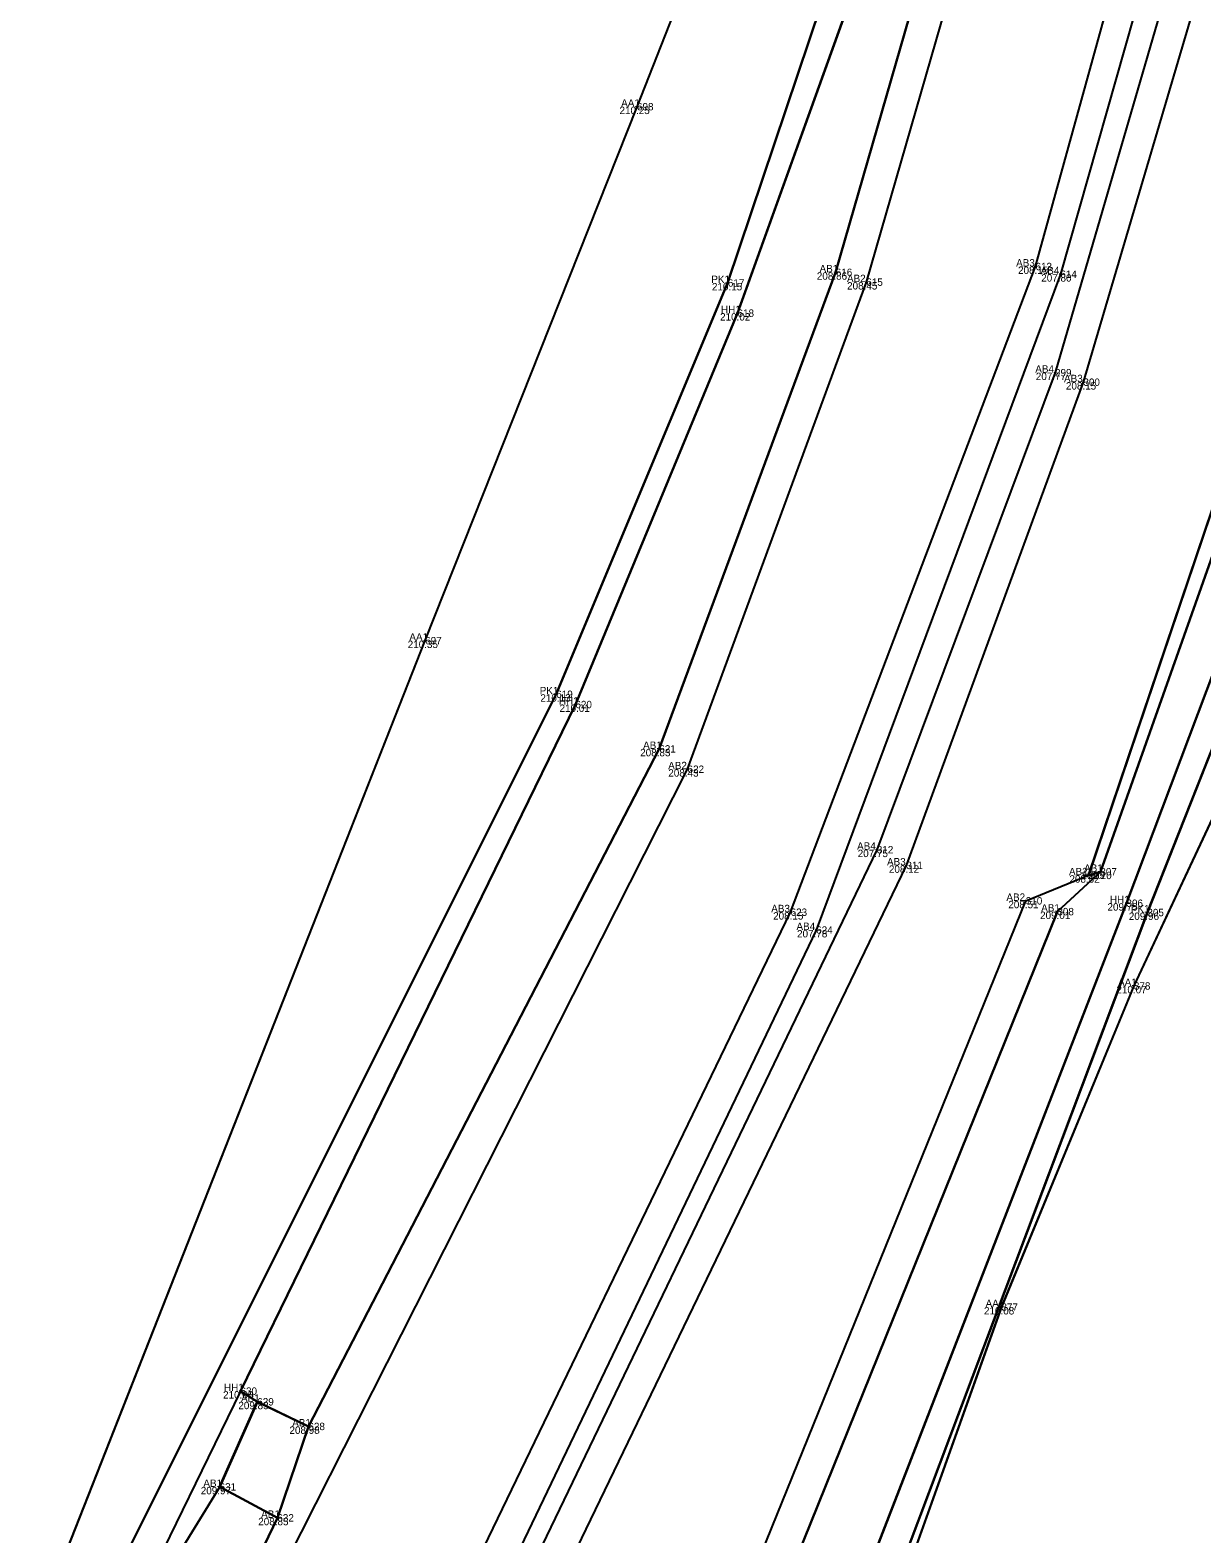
# Model space of a CAD drawing. Extents: x -263091 to -262565, y -1238731 to -1237092.
# Drawn here: x -262869.55 to -262837.85, y -1238112.64 to -1238071.97 of the extents above; entities that cross this region are included whole.
import ezdxf

# ---------------------------------------------------------------- set-up
doc = ezdxf.new("R2010")
doc.units = 0
for name, color, linetype in [('01_Hrana_betónu', 7, 'Continuous'), ('02_Oplotenie', 7, 'Continuous'), ('03_Asfalt', 7, 'Continuous'), ('05_Hrana_terénu', 7, 'Continuous'), ('07_Iné', 7, 'Continuous'), ('09_Múrik', 7, 'Continuous'), ('Groma (21)', 7, 'Continuous'), ('Groma (22)', 7, 'Continuous'), ('Groma (23)', 7, 'Continuous'), ('Groma (24)', 7, 'Continuous'), ('U003_Betónové_múriky', 7, 'Continuous'), ('U003_Betónové_panely', 7, 'Continuous'), ('U003_Betóny_prídavné', 7, 'Continuous'), ('U003_Zeleň_mimo', 7, 'Continuous'), ('U003_Zeleň_vnútro', 7, 'Continuous'), ('U003_Zeleň_zatrávňovač', 7, 'Continuous'), ('U005_Betóny_prídavné', 7, 'Continuous')]:
    doc.layers.add(name, color=color, linetype=linetype)

msp = doc.modelspace()

# ---------------------------------------------------------------- linework, layer by layer
at = {"layer": '01_Hrana_betónu'}
for points in [[(-262903.088, -1238238.797), (-262890.817, -1238204.479), (-262885.468, -1238189.492), (-262878.003, -1238168.56), (-262870.455, -1238147.513), (-262864.947, -1238132.168), (-262859.037, -1238116.651), (-262848.977, -1238095.826), (-262842.353, -1238078.361), (-262839.446, -1238067.823), (-262836.783, -1238055.069), (-262834.905, -1238040.999), (-262833.763, -1238025.462), (-262832.297, -1238000.555), (-262831.13, -1237981.111), (-262829.791, -1237958.391), (-262828.651, -1237937.03), (-262828.571, -1237935.876)], [(-262827.762, -1237935.927), (-262827.853, -1237937.062), (-262829.049, -1237958.415), (-262830.305, -1237981.211), (-262831.433, -1238000.629), (-262832.987, -1238025.43), (-262834.086, -1238041.027), (-262836.169, -1238055.023), (-262838.684, -1238068.024), (-262841.681, -1238078.569), (-262848.285, -1238096.308), (-262858.162, -1238116.913), (-262863.876, -1238132.122), (-262869.919, -1238147.692), (-262877.244, -1238168.638), (-262884.69, -1238189.67), (-262901.991, -1238238.762)], [(-262827.034, -1237935.973), (-262827.072, -1237937.036), (-262828.491, -1237960.168), (-262829.643, -1237980.454), (-262830.754, -1238002.123), (-262832.4, -1238026.024), (-262833.369, -1238041.644), (-262835.263, -1238055.011), (-262838.048, -1238068.261), (-262841.826, -1238081.232), (-262846.645, -1238094.136), (-262857.777, -1238117.273), (-262863.292, -1238131.948), (-262884.082, -1238190.299), (-262901.352, -1238238.742)], [(-262900.376, -1238238.711), (-262890.192, -1238209.46), (-262883.463, -1238190.564), (-262868.512, -1238148.877), (-262862.514, -1238132.276), (-262857.014, -1238117.706), (-262845.846, -1238094.561), (-262841.058, -1238081.49), (-262837.218, -1238068.474), (-262834.492, -1238055.416), (-262832.606, -1238041.772), (-262831.509, -1238026.143), (-262830.024, -1238002.24), (-262828.826, -1237980.518), (-262827.576, -1237960.277), (-262826.117, -1237937.218), (-262826.079, -1237936.033)], [(-262908.762, -1238238.978), (-262904.818, -1238227.708), (-262897.756, -1238208.088), (-262895.676, -1238202.213), (-262890.59, -1238187.74), (-262883.178, -1238166.691), (-262875.605, -1238145.524), (-262870.177, -1238130.111), (-262864.546, -1238115.411), (-262863.698, -1238113.971), (-262862.86, -1238112.208), (-262862.02, -1238109.736), (-262852.529, -1238091.409), (-262847.756, -1238078.518), (-262845.507, -1238070.714), (-262845.277, -1238070.627)], [(-262907.715, -1238238.945), (-262903.959, -1238228.072), (-262896.871, -1238208.378), (-262894.873, -1238202.609), (-262889.743, -1238188.028), (-262882.328, -1238167.085), (-262874.744, -1238145.867), (-262869.274, -1238130.427), (-262863.367, -1238114.899), (-262851.765, -1238091.959), (-262846.929, -1238078.783), (-262844.647, -1238070.871), (-262844.833, -1238070.767)], [(-262896.34, -1238238.582), (-262893.58, -1238232.03), (-262890.694, -1238224.883), (-262885.46, -1238210.629), (-262879.076, -1238191.844), (-262872.3, -1238172.74), (-262864.174, -1238150.334), (-262858.102, -1238133.93), (-262852.288, -1238119.39), (-262842.616, -1238095.519), (-262840.924, -1238094.827)], [(-262895.195, -1238238.545), (-262892.745, -1238232.498), (-262889.857, -1238225.243), (-262884.61, -1238210.939), (-262878.158, -1238192.142), (-262871.406, -1238173.111), (-262863.323, -1238150.734), (-262857.2, -1238134.123), (-262851.463, -1238119.84), (-262841.762, -1238095.81), (-262840.6, -1238094.732)]]:
    msp.add_lwpolyline(points, dxfattribs=at)
at = {"layer": '02_Oplotenie'}
for points in [[(-262912.451, -1238238.295), (-262908.254, -1238226.663), (-262901.526, -1238207.942), (-262898.552, -1238199.602), (-262894.22, -1238186.327), (-262886.794, -1238165.648), (-262879.297, -1238144.201), (-262873.976, -1238128.814), (-262867.141, -1238113.572), (-262855.316, -1238089.931), (-262850.675, -1238078.807), (-262846.261, -1238065.654), (-262843.56, -1238054.226), (-262842.344, -1238048.099), (-262841.445, -1238040.349), (-262840.733, -1238030.077), (-262839.013, -1238000.384), (-262838.353, -1237989.712), (-262835.178, -1237935.879)], [(-262819.762, -1237938.034), (-262820.788, -1237960.675), (-262821.837, -1237980.919), (-262823.308, -1238002.106), (-262824.582, -1238026.068), (-262825.82, -1238041.973), (-262827.772, -1238056.552), (-262830.57, -1238069.546), (-262834.589, -1238083.855), (-262839.328, -1238095.835), (-262848.782, -1238120.942), (-262853.684, -1238135.175), (-262859.896, -1238152.781), (-262867.698, -1238174.329), (-262874.833, -1238193.487), (-262881.88, -1238212.036), (-262887.174, -1238225.693), (-262888.829, -1238230.138)]]:
    msp.add_lwpolyline(points, dxfattribs=at)
at = {"layer": '03_Asfalt'}
for points in [[(-262912.678, -1238239.103), (-262913.356, -1238239.285), (-262915.717, -1238239.279), (-262916.328, -1238238.784), (-262916.575, -1238236.319), (-262915.768, -1238233.661), (-262912.404, -1238225.097), (-262904.805, -1238205.606), (-262896.687, -1238184.948), (-262888.478, -1238163.929), (-262880.124, -1238142.63), (-262874.65, -1238128.675), (-262868.549, -1238113.075), (-262858.861, -1238088.481), (-262853.132, -1238074.038), (-262850.084, -1238066.288), (-262845.869, -1238049.471), (-262845.094, -1238038.662), (-262844.346, -1238028.542), (-262842.599, -1238000.955), (-262841.603, -1237985.168), (-262838.824, -1237943.888), (-262838.24, -1237934.633), (-262838.283, -1237933.488)], [(-262836.859, -1238089.782), (-262836.111, -1238090.171), (-262839.692, -1238097.821), (-262843.275, -1238106.507), (-262847.806, -1238119.202), (-262853.613, -1238135.97), (-262859.461, -1238152.467), (-262860.389, -1238156.54), (-262862.798, -1238164.04), (-262866.716, -1238174.359), (-262874.069, -1238193.289), (-262881.205, -1238211.833), (-262885.932, -1238224.211), (-262887.38, -1238228.337), (-262891.202, -1238238.204), (-262891.593, -1238238.614)]]:
    msp.add_lwpolyline(points, dxfattribs=at)
at = {"layer": '05_Hrana_terénu'}
for points in [[(-262835.062, -1237935.275), (-262834.86, -1237936.333), (-262838.087, -1237989.633), (-262838.484, -1238000.332), (-262840.387, -1238030.181), (-262840.991, -1238040.253), (-262843.126, -1238054.282), (-262845.675, -1238066.436), (-262850.413, -1238079.623), (-262854.798, -1238090.209), (-262863.856, -1238108.78), (-262866.643, -1238114.502), (-262872.333, -1238129.41), (-262877.981, -1238144.625), (-262885.616, -1238166.033), (-262893.121, -1238186.676), (-262898.244, -1238201.149), (-262900.554, -1238208.001), (-262907.375, -1238226.781), (-262911.85, -1238238.364), (-262912.678, -1238239.103)], [(-262849.564, -1238120.544), (-262839.894, -1238095.583), (-262835.301, -1238083.403), (-262831.402, -1238069.334), (-262828.632, -1238056.516), (-262826.436, -1238041.83), (-262825.08, -1238026.06), (-262823.863, -1238001.967), (-262822.633, -1237980.847), (-262821.298, -1237960.54), (-262820.334, -1237939.047), (-262819.871, -1237937.657)]]:
    msp.add_lwpolyline(points, dxfattribs=at)
at = {"layer": '07_Iné'}
msp.add_lwpolyline([(-262862.86, -1238112.208), (-262864.423, -1238111.371), (-262863.403, -1238109.069), (-262862.02, -1238109.736)], dxfattribs=at)
at = {"layer": '09_Múrik'}
for points in [[(-262840.924, -1238094.827), (-262836.941, -1238083.068), (-262832.969, -1238069.042), (-262830.214, -1238056.416), (-262828.063, -1238041.942), (-262826.83, -1238026.465), (-262825.494, -1238001.855), (-262824.316, -1237980.84), (-262823.031, -1237960.337), (-262821.719, -1237936.336)], [(-262840.6, -1238094.732), (-262836.43, -1238082.967), (-262832.633, -1238069.1), (-262829.86, -1238056.421), (-262827.688, -1238042.018), (-262826.338, -1238026.448), (-262825.108, -1238001.872), (-262823.89, -1237980.741), (-262822.602, -1237960.47), (-262821.253, -1237936.39)]]:
    msp.add_lwpolyline(points, dxfattribs=at)
at = {"layer": 'Groma (21)'}
for centre in [(-262853.132, -1238074.038), (-262847.756, -1238078.518), (-262842.353, -1238078.361), (-262841.681, -1238078.569), (-262850.675, -1238078.807), (-262846.929, -1238078.783), (-262850.413, -1238079.623), (-262841.826, -1238081.232), (-262841.058, -1238081.49), (-262858.861, -1238088.481), (-262855.316, -1238089.931), (-262854.798, -1238090.209), (-262852.529, -1238091.409), (-262851.765, -1238091.959), (-262846.645, -1238094.136), (-262845.846, -1238094.561), (-262840.924, -1238094.827), (-262840.6, -1238094.732), (-262842.616, -1238095.519), (-262839.894, -1238095.583), (-262848.977, -1238095.826), (-262841.762, -1238095.81), (-262839.328, -1238095.835), (-262848.285, -1238096.308), (-262839.692, -1238097.821), (-262843.275, -1238106.507), (-262863.856, -1238108.78), (-262863.403, -1238109.069), (-262862.02, -1238109.736), (-262864.423, -1238111.371), (-262862.86, -1238112.208)]:
    msp.add_circle(centre, 0.01, dxfattribs=at)
at = {"layer": 'U003_Betónové_múriky'}
msp.add_lwpolyline([(-262821.25, -1237936.39), (-262822.6, -1237960.47), (-262823.89, -1237980.74), (-262825.11, -1238001.87), (-262826.34, -1238026.45), (-262827.69, -1238042.02), (-262829.86, -1238056.42), (-262832.63, -1238069.1), (-262836.43, -1238082.97), (-262840.6, -1238094.73), (-262840.92, -1238094.83), (-262836.94, -1238083.07), (-262832.97, -1238069.04), (-262830.21, -1238056.42), (-262828.06, -1238041.94), (-262826.83, -1238026.47), (-262825.49, -1238001.86), (-262824.32, -1237980.84), (-262823.03, -1237960.34), (-262821.72, -1237936.34)], close=True, dxfattribs=at)
msp.add_lwpolyline([(-262821.72, -1237936.34), (-262821.25, -1237936.39), (-262822.6, -1237960.47), (-262823.89, -1237980.74), (-262825.11, -1238001.87), (-262826.34, -1238026.45), (-262827.69, -1238042.02), (-262829.86, -1238056.42), (-262832.63, -1238069.1), (-262836.43, -1238082.97), (-262840.6, -1238094.73), (-262840.92, -1238094.83), (-262836.94, -1238083.07), (-262832.97, -1238069.04), (-262830.21, -1238056.42), (-262828.06, -1238041.94), (-262826.83, -1238026.47), (-262825.49, -1238001.86), (-262824.32, -1237980.84), (-262823.03, -1237960.34), (-262821.72, -1237936.34)], dxfattribs=at)
at = {"layer": 'U003_Betónové_panely'}
for points in [[(-262863.7, -1238113.97), (-262862.86, -1238112.21), (-262862.02, -1238109.74), (-262852.53, -1238091.41), (-262847.76, -1238078.52), (-262845.51, -1238070.71), (-262845.28, -1238070.63), (-262844.83, -1238070.77), (-262843.91, -1238066.81), (-262841.25, -1238054.25), (-262839.31, -1238040.16), (-262838.49, -1238030.43), (-262836.61, -1238000.28), (-262836.05, -1237989.86), (-262834, -1237956.68), (-262832.67, -1237935.62), (-262832.64, -1237935.62), (-262832.51, -1237933.84)], [(-262863.7, -1238113.97), (-262862.86, -1238112.21), (-262862.02, -1238109.74), (-262852.53, -1238091.41), (-262847.76, -1238078.52), (-262845.51, -1238070.71), (-262845.28, -1238070.63), (-262844.83, -1238070.77), (-262843.91, -1238066.81), (-262841.25, -1238054.25), (-262839.31, -1238040.16), (-262838.49, -1238030.43), (-262836.61, -1238000.28), (-262836.05, -1237989.86), (-262834, -1237956.68), (-262832.67, -1237935.62), (-262832.64, -1237935.62), (-262832.51, -1237933.84)], [(-262822, -1237934.47), (-262822.23, -1237936.28), (-262821.72, -1237936.34), (-262823.03, -1237960.34), (-262824.32, -1237980.84), (-262825.49, -1238001.86), (-262826.83, -1238026.47), (-262828.06, -1238041.94), (-262830.21, -1238056.42), (-262832.97, -1238069.04), (-262836.94, -1238083.07), (-262840.92, -1238094.83), (-262840.6, -1238094.73), (-262841.76, -1238095.81), (-262851.46, -1238119.84), (-262857.2, -1238134.12), (-262863.32, -1238150.73), (-262871.41, -1238173.11), (-262878.16, -1238192.14), (-262884.61, -1238210.94), (-262889.86, -1238225.24), (-262892.75, -1238232.5), (-262895.19, -1238238.55), (-262900.83, -1238252.4)], [(-262822, -1237934.47), (-262822.23, -1237936.28), (-262821.72, -1237936.34), (-262823.03, -1237960.34), (-262824.32, -1237980.84), (-262825.49, -1238001.86), (-262826.83, -1238026.47), (-262828.06, -1238041.94), (-262830.21, -1238056.42), (-262832.97, -1238069.04), (-262836.94, -1238083.07), (-262840.92, -1238094.83), (-262840.6, -1238094.73), (-262841.76, -1238095.81), (-262851.46, -1238119.84), (-262857.2, -1238134.12), (-262863.32, -1238150.73), (-262871.41, -1238173.11), (-262878.16, -1238192.14), (-262884.61, -1238210.94), (-262889.86, -1238225.24), (-262892.75, -1238232.5), (-262895.19, -1238238.55), (-262900.83, -1238252.4)]]:
    msp.add_lwpolyline(points, dxfattribs=at)
at = {"layer": 'U003_Betóny_prídavné'}
msp.add_lwpolyline([(-262864.42, -1238111.37), (-262863.4, -1238109.07), (-262862.02, -1238109.74), (-262862.86, -1238112.21)], close=True, dxfattribs=at)
at = {"layer": 'U003_Zeleň_mimo'}
for points in [[(-262868.55, -1238113.08), (-262858.86, -1238088.48), (-262853.13, -1238074.04), (-262850.08, -1238066.29), (-262845.87, -1238049.47), (-262845.09, -1238038.66), (-262844.35, -1238028.54), (-262842.6, -1238000.96), (-262841.6, -1237985.17), (-262838.82, -1237943.89), (-262838.24, -1237934.63)], [(-262836.32, -1237934.59), (-262836.29, -1237935.17), (-262835.06, -1237935.28), (-262835.18, -1237935.88), (-262838.35, -1237989.71), (-262839.01, -1238000.38), (-262840.73, -1238030.08), (-262841.45, -1238040.35), (-262842.34, -1238048.1), (-262843.56, -1238054.23), (-262846.26, -1238065.65), (-262850.68, -1238078.81), (-262855.32, -1238089.93), (-262867.14, -1238113.57)], [(-262848.78, -1238120.94), (-262839.33, -1238095.84), (-262834.59, -1238083.86), (-262836.86, -1238089.78), (-262836.11, -1238090.17), (-262839.69, -1238097.82), (-262843.28, -1238106.51), (-262847.81, -1238119.2)]]:
    msp.add_lwpolyline(points, dxfattribs=at)
at = {"layer": 'U003_Zeleň_vnútro'}
for points in [[(-262849.56, -1238120.54), (-262839.89, -1238095.58), (-262835.3, -1238083.4), (-262831.4, -1238069.33), (-262828.63, -1238056.52), (-262826.44, -1238041.83), (-262825.08, -1238026.06), (-262823.86, -1238001.97), (-262822.63, -1237980.85), (-262821.3, -1237960.54), (-262820.33, -1237939.05), (-262819.87, -1237937.66), (-262819.76, -1237938.03), (-262820.79, -1237960.68), (-262821.84, -1237980.92), (-262823.31, -1238002.11), (-262824.58, -1238026.07), (-262825.82, -1238041.97), (-262827.77, -1238056.55), (-262830.57, -1238069.55), (-262834.59, -1238083.86), (-262839.33, -1238095.84), (-262848.78, -1238120.94)], [(-262849.56, -1238120.54), (-262839.89, -1238095.58), (-262835.3, -1238083.4), (-262831.4, -1238069.33), (-262828.63, -1238056.52), (-262826.44, -1238041.83), (-262825.08, -1238026.06), (-262823.86, -1238001.97), (-262822.63, -1237980.85), (-262821.3, -1237960.54), (-262820.33, -1237939.05), (-262819.87, -1237937.66), (-262819.76, -1237938.03), (-262820.79, -1237960.68), (-262821.84, -1237980.92), (-262823.31, -1238002.11), (-262824.58, -1238026.07), (-262825.82, -1238041.97), (-262827.77, -1238056.55), (-262830.57, -1238069.55), (-262834.59, -1238083.86), (-262839.33, -1238095.84), (-262848.78, -1238120.94)], [(-262867.14, -1238113.57), (-262855.32, -1238089.93), (-262850.68, -1238078.81), (-262846.26, -1238065.65), (-262843.56, -1238054.23), (-262842.34, -1238048.1), (-262841.45, -1238040.35), (-262840.73, -1238030.08), (-262839.01, -1238000.38)], [(-262867.14, -1238113.57), (-262855.32, -1238089.93), (-262850.68, -1238078.81), (-262846.26, -1238065.65), (-262843.56, -1238054.23), (-262842.34, -1238048.1), (-262841.45, -1238040.35), (-262840.73, -1238030.08), (-262839.01, -1238000.38)], [(-262838.48, -1238000.33), (-262840.39, -1238030.18), (-262840.99, -1238040.25), (-262843.13, -1238054.28), (-262845.68, -1238066.44), (-262850.41, -1238079.62), (-262854.8, -1238090.21), (-262863.86, -1238108.78), (-262863.4, -1238109.07), (-262864.42, -1238111.37), (-262865.55, -1238113.22)], [(-262838.48, -1238000.33), (-262840.39, -1238030.18), (-262840.99, -1238040.25), (-262843.13, -1238054.28), (-262845.68, -1238066.44), (-262850.41, -1238079.62), (-262854.8, -1238090.21), (-262863.86, -1238108.78), (-262863.4, -1238109.07), (-262864.42, -1238111.37), (-262865.55, -1238113.22)]]:
    msp.add_lwpolyline(points, dxfattribs=at)
at = {"layer": 'U003_Zeleň_zatrávňovač'}
for points in [[(-262836.98, -1238000.41), (-262838.75, -1238030.68), (-262839.65, -1238040.29), (-262841.58, -1238054.27), (-262844.22, -1238066.74), (-262845.28, -1238070.63), (-262845.51, -1238070.71), (-262847.76, -1238078.52), (-262852.53, -1238091.41), (-262862.02, -1238109.74), (-262863.4, -1238109.07), (-262863.86, -1238108.78), (-262854.8, -1238090.21), (-262850.41, -1238079.62), (-262845.68, -1238066.44), (-262843.13, -1238054.28), (-262840.99, -1238040.25), (-262840.39, -1238030.18), (-262838.48, -1238000.33)], [(-262862.02, -1238109.74), (-262863.4, -1238109.07), (-262863.86, -1238108.78), (-262854.8, -1238090.21), (-262850.41, -1238079.62), (-262845.68, -1238066.44), (-262843.13, -1238054.28), (-262840.99, -1238040.25), (-262840.39, -1238030.18), (-262838.48, -1238000.33)], [(-262836.98, -1238000.41), (-262838.75, -1238030.68), (-262839.65, -1238040.29), (-262841.58, -1238054.27), (-262844.22, -1238066.74), (-262845.28, -1238070.63), (-262845.51, -1238070.71), (-262847.76, -1238078.52), (-262852.53, -1238091.41), (-262862.02, -1238109.74)], [(-262851.46, -1238119.84), (-262841.76, -1238095.81), (-262840.6, -1238094.73), (-262836.43, -1238082.97), (-262832.63, -1238069.1), (-262829.86, -1238056.42), (-262827.69, -1238042.02), (-262826.34, -1238026.45), (-262825.11, -1238001.87)], [(-262823.86, -1238001.97), (-262825.08, -1238026.06), (-262826.44, -1238041.83), (-262828.63, -1238056.52), (-262831.4, -1238069.33), (-262835.3, -1238083.4), (-262839.89, -1238095.58), (-262849.56, -1238120.54)]]:
    msp.add_lwpolyline(points, dxfattribs=at)
msp.add_lwpolyline([(-262863.7, -1238113.97), (-262865.55, -1238113.22), (-262864.42, -1238111.37), (-262862.86, -1238112.21)], close=True, dxfattribs=at)
at = {"layer": 'U005_Betóny_prídavné'}
for points in [[(-262851.46, -1238119.84), (-262841.76, -1238095.81), (-262840.6, -1238094.73), (-262836.43, -1238082.97), (-262832.63, -1238069.1), (-262829.86, -1238056.42), (-262827.69, -1238042.02), (-262826.34, -1238026.45), (-262825.11, -1238001.87)], [(-262823.86, -1238001.97), (-262825.08, -1238026.06), (-262826.44, -1238041.83), (-262828.63, -1238056.52), (-262831.4, -1238069.33), (-262835.3, -1238083.4), (-262839.89, -1238095.58), (-262849.56, -1238120.54)]]:
    msp.add_lwpolyline(points, dxfattribs=at)

# ---------------------------------------------------------------- texts
at = {"layer": 'Groma (22)'}
for s, p in [('698', (-262853.132, -1238074.138)), ('616', (-262847.756, -1238078.618)), ('613', (-262842.353, -1238078.461)), ('614', (-262841.681, -1238078.669)), ('617', (-262850.675, -1238078.907)), ('615', (-262846.929, -1238078.883)), ('618', (-262850.413, -1238079.723)), ('299', (-262841.826, -1238081.332)), ('300', (-262841.058, -1238081.59)), ('697', (-262858.861, -1238088.581)), ('619', (-262855.316, -1238090.031)), ('620', (-262854.798, -1238090.309)), ('621', (-262852.529, -1238091.509)), ('622', (-262851.765, -1238092.059)), ('312', (-262846.645, -1238094.236)), ('311', (-262845.846, -1238094.661)), ('309', (-262840.924, -1238094.927)), ('307', (-262840.6, -1238094.832)), ('310', (-262842.616, -1238095.619)), ('308', (-262841.762, -1238095.91)), ('306', (-262839.894, -1238095.683)), ('623', (-262848.977, -1238095.926)), ('305', (-262839.328, -1238095.935)), ('624', (-262848.285, -1238096.408)), ('378', (-262839.692, -1238097.921)), ('377', (-262843.275, -1238106.607)), ('630', (-262863.856, -1238108.88)), ('629', (-262863.403, -1238109.169)), ('628', (-262862.02, -1238109.836)), ('631', (-262864.423, -1238111.471)), ('632', (-262862.86, -1238112.308))]:
    msp.add_text(s, height=0.2, dxfattribs=at).set_placement(p)
at = {"layer": 'Groma (23)'}
for s, p in [('210.25', (-262853.605, -1238074.238)), ('208.86', (-262848.268, -1238078.718)), ('208.15', (-262842.826, -1238078.561)), ('207.80', (-262842.198, -1238078.769)), ('210.15', (-262851.105, -1238079.007)), ('208.45', (-262847.45, -1238078.983)), ('210.02', (-262850.885, -1238079.823)), ('207.77', (-262842.345, -1238081.432)), ('208.15', (-262841.531, -1238081.69)), ('210.35', (-262859.334, -1238088.681)), ('210.13', (-262855.746, -1238090.131)), ('210.01', (-262855.227, -1238090.409)), ('208.83', (-262853.046, -1238091.609)), ('208.43', (-262852.286, -1238092.159)), ('207.75', (-262847.163, -1238094.336)), ('208.12', (-262846.319, -1238094.761)), ('208.62', (-262841.436, -1238095.027)), ('209.20', (-262841.111, -1238094.932)), ('208.51', (-262843.089, -1238095.719)), ('209.75', (-262840.407, -1238095.783)), ('208.15', (-262849.45, -1238096.026)), ('209.01', (-262842.23, -1238096.01)), ('209.96', (-262839.83, -1238096.035)), ('207.78', (-262848.803, -1238096.508)), ('210.07', (-262840.165, -1238098.021)), ('210.08', (-262843.747, -1238106.707)), ('210.00', (-262864.328, -1238108.98)), ('209.83', (-262863.915, -1238109.269)), ('208.98', (-262862.532, -1238109.936)), ('209.97', (-262864.931, -1238111.571)), ('208.85', (-262863.377, -1238112.408))]:
    msp.add_text(s, height=0.2, dxfattribs=at).set_placement(p)
at = {"layer": 'Groma (24)'}
for s, p in [('AA1', (-262853.56, -1238074.038)), ('AB3', (-262842.877, -1238078.361)), ('PK1', (-262851.122, -1238078.807)), ('AB1', (-262848.194, -1238078.518)), ('AB2', (-262847.453, -1238078.783)), ('AB4', (-262842.215, -1238078.569)), ('HH1', (-262850.86, -1238079.623)), ('AB4', (-262842.36, -1238081.232)), ('AB3', (-262841.582, -1238081.49)), ('AA1', (-262859.289, -1238088.481)), ('PK1', (-262855.763, -1238089.931)), ('HH1', (-262855.245, -1238090.209)), ('AB1', (-262852.967, -1238091.409)), ('AB2', (-262852.289, -1238091.959)), ('AB4', (-262847.179, -1238094.136)), ('AB3', (-262846.37, -1238094.561)), ('AB2', (-262841.448, -1238094.827)), ('AB1', (-262841.038, -1238094.732)), ('AB3', (-262849.501, -1238095.826)), ('AB2', (-262843.14, -1238095.519)), ('AB1', (-262842.2, -1238095.81)), ('HH1', (-262840.341, -1238095.583)), ('PK1', (-262839.775, -1238095.835)), ('AB4', (-262848.819, -1238096.308)), ('AA1', (-262840.12, -1238097.821)), ('AA1', (-262843.703, -1238106.507)), ('HH1', (-262864.303, -1238108.78)), ('AB1', (-262863.841, -1238109.069)), ('AB1', (-262862.458, -1238109.736)), ('AB1', (-262864.861, -1238111.371)), ('AB1', (-262863.298, -1238112.208))]:
    msp.add_text(s, height=0.2, dxfattribs=at).set_placement(p)

doc.saveas('drawing.dxf')
